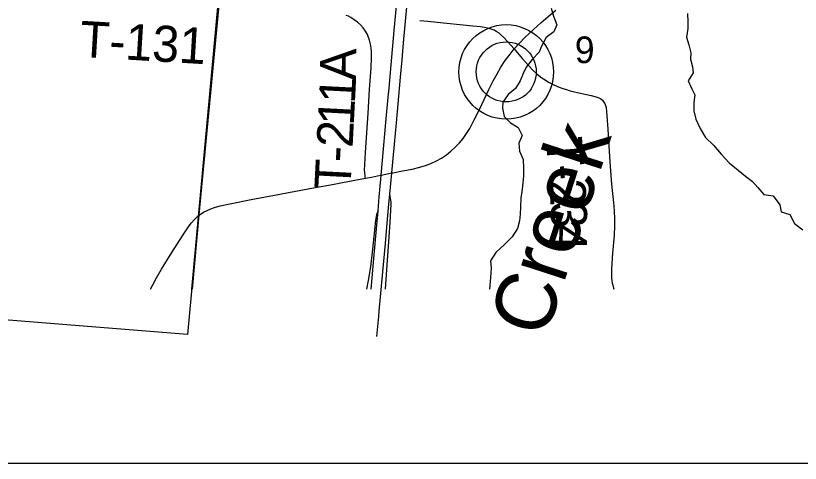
# Model space of a CAD drawing. Extents: x 0 to 34, y 0 to 22.
# Drawn here: x 6.536 to 7.77, y 17.5 to 18.205 of the extents above; entities that cross this region are included whole.
import ezdxf

# ---------------------------------------------------------------- set-up
doc = ezdxf.new("R2010")
doc.units = 0
for name, color, linetype in [('GM_X_Corporation', 7, 'Continuous'), ('GM_X_County_Road', 7, 'Continuous'), ('GM_X_Interchange_Ramps', 7, 'Continuous'), ('GM_X_Minor_River', 7, 'Continuous'), ('GM_X_Minor_River_Text', 7, 'Continuous'), ('GM_X_Section_Text', 7, 'Continuous'), ('GM_X_Township_Road', 7, 'Continuous'), ('GM_X_Township_Road_Text', 7, 'Continuous'), ('GM_X_Unincorporated', 7, 'Continuous'), ('GM_X_Unincorporated_Location', 7, 'Continuous'), ('GM_X_US_Route', 7, 'Continuous'), ('SH_Data', 7, 'Continuous')]:
    doc.layers.add(name, color=color, linetype=linetype)

msp = doc.modelspace()

# ---------------------------------------------------------------- linework, layer by layer
at = {"layer": 'GM_X_Corporation'}
for points in [[(6.8137, 17.7739), (6.8245, 17.8909), (6.8563, 18.2261), (6.9053, 18.781), (6.9106, 18.8306), (6.9204, 18.908), (6.8775, 18.9245), (6.8626, 18.9279), (6.8089, 18.9336), (6.7895, 18.937), (6.762, 18.9484), (6.7095, 18.9576), (6.6683, 18.9564), (6.6317, 18.9678), (6.5552, 18.9793), (6.4809, 18.9953)], [(6.4809, 18.9953), (6.5552, 18.9793), (6.6317, 18.9678), (6.6683, 18.9564), (6.7095, 18.9576), (6.762, 18.9484), (6.7895, 18.937), (6.8089, 18.9336), (6.8626, 18.9279), (6.8775, 18.9245), (6.9204, 18.908), (6.9106, 18.8306), (6.9053, 18.781), (6.8563, 18.2261), (6.8245, 17.8909), (6.8137, 17.7739)], [(6.8132, 17.7739), (6.9001, 18.7194), (7.9102, 18.6438), (7.8167, 17.7739)]]:
    msp.add_lwpolyline(points, dxfattribs=at)
msp.add_lwpolyline([(5.8857, 18.8), (6.9001, 18.7194), (6.8066, 17.7025), (5.8048, 17.783)], close=True, dxfattribs=at)
at = {"layer": 'GM_X_County_Road'}
for points in [[(7.0862, 17.9488), (7.0959, 17.9506), (7.105, 17.9524), (7.1112, 17.9537), (7.1278, 17.957), (7.1294, 17.9573), (7.1446, 17.9602), (7.1598, 17.9632), (7.1718, 17.9662), (7.1807, 17.9689), (7.1893, 17.9721), (7.1978, 17.9759), (7.2059, 17.9804), (7.2136, 17.9855), (7.2208, 17.9912), (7.2276, 17.9975), (7.234, 18.0042), (7.2399, 18.0113), (7.2453, 18.0189), (7.2502, 18.0267), (7.2575, 18.0404), (7.2657, 18.0571), (7.2802, 18.0881), (7.2872, 18.102), (7.2932, 18.1131), (7.2994, 18.1236), (7.3062, 18.1341), (7.3137, 18.1441), (7.3204, 18.1524), (7.3283, 18.1613), (7.337, 18.1701), (7.3504, 18.1829), (7.3619, 18.1932), (7.3737, 18.2034), (7.3855, 18.2134)], [(7.0372, 17.9396), (7.0501, 17.9421), (7.0862, 17.9488)], [(6.8248, 17.8903), (6.8264, 17.8916), (6.8317, 17.8951), (6.8373, 17.898), (6.843, 17.9006), (6.8489, 17.9027), (6.858, 17.9052), (6.8732, 17.9085), (6.9066, 17.9152), (6.9433, 17.9221), (6.9738, 17.9279), (7.0044, 17.9334), (7.0372, 17.9396)], [(6.7482, 17.7739), (6.7517, 17.7811), (6.7576, 17.7921), (6.7654, 17.8055), (6.7818, 17.8319), (6.7986, 17.8581), (6.8091, 17.8736), (6.8129, 17.8786), (6.817, 17.8833), (6.8215, 17.8877), (6.8248, 17.8903)]]:
    msp.add_lwpolyline(points, dxfattribs=at)
at = {"layer": 'GM_X_Interchange_Ramps'}
for points in [[(7.1176, 17.7739), (7.1181, 17.7819), (7.1208, 17.8199), (7.1228, 17.8485), (7.1251, 17.8797), (7.1269, 17.9076), (7.1267, 17.9111), (7.1263, 17.914), (7.1247, 17.9238)], [(7.1062, 17.8976), (7.1042, 17.8927), (7.1036, 17.891), (7.103, 17.8883), (7.102, 17.8821), (7.0975, 17.8371), (7.094, 17.8093), (7.0908, 17.7877), (7.0882, 17.7739)]]:
    msp.add_lwpolyline(points, dxfattribs=at)
at = {"layer": 'GM_X_Minor_River'}
for points in [[(7.3781, 18.2165), (7.3821, 18.2039), (7.3873, 18.1899), (7.3823, 18.1793), (7.3705, 18.1703), (7.3629, 18.1567), (7.3594, 18.1469), (7.3487, 18.1356), (7.3388, 18.1235), (7.3342, 18.1133), (7.3295, 18.102), (7.3223, 18.0899), (7.3105, 18.0805), (7.3021, 18.0684), (7.302, 18.0589), (7.3042, 18.046), (7.3143, 18.0357), (7.3267, 18.0284), (7.3327, 18.0159), (7.3277, 18.0038), (7.3283, 17.9913), (7.3343, 17.9783), (7.3349, 17.9643), (7.3349, 17.9518), (7.334, 17.9412), (7.3328, 17.9313), (7.3308, 17.9173), (7.33, 17.9037), (7.3295, 17.8919), (7.3287, 17.8817), (7.3255, 17.8696), (7.3171, 17.8567), (7.3053, 17.8451), (7.2912, 17.8319), (7.2828, 17.8187)], [(7.5929, 18.2081), (7.5935, 18.1948), (7.5935, 18.1846), (7.5911, 18.1709), (7.5948, 18.1588), (7.5981, 18.1459), (7.5976, 18.136), (7.6006, 18.1238), (7.6016, 18.1144), (7.594, 18.1019), (7.5996, 18.0894), (7.6044, 18.0798), (7.6028, 18.0681), (7.6027, 18.0548), (7.606, 18.0419), (7.6127, 18.0267), (7.6209, 18.013), (7.6344, 18.0004), (7.6457, 17.9866), (7.6585, 17.9729), (7.684, 17.9522), (7.6949, 17.9434), (7.7036, 17.9339), (7.7129, 17.9232), (7.7273, 17.9208), (7.7378, 17.9067), (7.7403, 17.8957), (7.7539, 17.8914), (7.761, 17.8777), (7.7742, 17.8674)], [(7.2828, 17.8187), (7.2838, 17.8069), (7.283, 17.7922), (7.2821, 17.7797), (7.2812, 17.7739)]]:
    msp.add_lwpolyline(points, dxfattribs=at)
at = {"layer": 'GM_X_Township_Road'}
for points in [[(7.0862, 17.9488), (7.086, 17.9509), (7.0851, 17.9582), (7.0849, 17.9611), (7.0865, 17.989), (7.0906, 18.051), (7.0929, 18.0882), (7.0952, 18.1224), (7.0959, 18.138), (7.0958, 18.1474), (7.0953, 18.1536), (7.0943, 18.1598), (7.0928, 18.166), (7.0908, 18.1719), (7.0895, 18.1748), (7.088, 18.1777), (7.0864, 18.1804), (7.0826, 18.1855), (7.0784, 18.1901), (7.0737, 18.1944), (7.0687, 18.1982), (7.0633, 18.2015), (7.0596, 18.2036), (7.0562, 18.205)], [(7.3204, 18.1524), (7.3096, 18.1639), (7.3033, 18.1707), (7.2989, 18.175), (7.2965, 18.177), (7.2931, 18.1793), (7.2885, 18.1816), (7.2839, 18.1833), (7.2782, 18.1848), (7.2735, 18.1858), (7.2674, 18.1868), (7.2551, 18.1881), (7.2397, 18.1898), (7.2088, 18.1927), (7.1842, 18.1953), (7.1718, 18.1963)], [(7.3204, 18.1524), (7.333, 18.1373), (7.3433, 18.1257), (7.3497, 18.1189), (7.3565, 18.1127), (7.3637, 18.1069), (7.3688, 18.1034), (7.374, 18.1001), (7.3823, 18.0959), (7.3907, 18.0921), (7.3967, 18.0899), (7.4023, 18.0881), (7.4083, 18.0864), (7.4264, 18.0823), (7.4415, 18.0787), (7.4505, 18.0762), (7.4534, 18.075), (7.4563, 18.0735), (7.4589, 18.0713), (7.4609, 18.069), (7.4626, 18.0662), (7.4638, 18.0632), (7.4646, 18.0601), (7.4654, 18.0538), (7.4674, 18.0259), (7.4702, 17.9826), (7.4712, 17.9671), (7.4733, 17.9393), (7.4742, 17.9296), (7.4751, 17.9197), (7.4768, 17.9053), (7.4776, 17.896), (7.478, 17.8866), (7.478, 17.8772), (7.4777, 17.871), (7.4774, 17.8617), (7.4772, 17.8586), (7.4748, 17.8307), (7.4734, 17.806), (7.4732, 17.7967), (7.4733, 17.7915), (7.4737, 17.7879), (7.4744, 17.7834), (7.4752, 17.7803), (7.4764, 17.7755), (7.4769, 17.7739)]]:
    msp.add_lwpolyline(points, dxfattribs=at)
at = {"layer": 'GM_X_Unincorporated'}
for radius in [0.0744, 0.0472]:
    msp.add_circle((7.3077, 18.116), radius, dxfattribs=at)
at = {"layer": 'GM_X_Unincorporated_Location'}
msp.add_line((7.3077, 18.116), (7.3077, 18.116), dxfattribs=at)
at = {"layer": 'GM_X_US_Route'}
for points in [[(7.1044, 17.6994), (7.1073, 17.7311), (7.1081, 17.7395), (7.1115, 17.7788), (7.1152, 17.8179), (7.1176, 17.8462), (7.1206, 17.8779), (7.1227, 17.9021), (7.1247, 17.9238), (7.1278, 17.957), (7.1321, 18.0024), (7.1349, 18.0359), (7.1375, 18.0658), (7.1413, 18.1076), (7.1438, 18.1349), (7.1462, 18.1617), (7.1512, 18.2181), (7.1525, 18.2332), (7.1535, 18.2451), (7.1563, 18.2771), (7.1587, 18.3023), (7.1643, 18.3633), (7.1665, 18.3876), (7.169, 18.4166)], [(7.0954, 17.7739), (7.0959, 17.7798), (7.0995, 17.8225), (7.1042, 17.8748), (7.1062, 17.8976), (7.1081, 17.9195), (7.1107, 17.9473), (7.1112, 17.9537), (7.1131, 17.9771), (7.1189, 18.042), (7.1221, 18.0764), (7.1234, 18.0907), (7.1268, 18.127), (7.1315, 18.1812), (7.1398, 18.2708)]]:
    msp.add_lwpolyline(points, dxfattribs=at)
at = {"layer": 'SH_Data'}
msp.add_line((2, 17.5), (9, 17.5), dxfattribs=at)

# ---------------------------------------------------------------- texts
at = {"layer": 'GM_X_Minor_River_Text'}
msp.add_text('Creek', height=0.09467, rotation=71.9853, dxfattribs=at).set_placement((7.3694, 17.6942))
at = {"layer": 'GM_X_Section_Text'}
msp.add_text('9', height=0.0419, rotation=0, dxfattribs=at).set_placement((7.4155, 18.1299))
at = {"layer": 'GM_X_Township_Road_Text'}
for s, height, rotation, p in [('T-131', 0.05682, 356.6344, (6.6359, 18.1398)), ('A', 0.0568, 89.0887, (7.0714, 18.1023)), ('1', 0.0568, 87.0482, (7.0696, 18.0654)), ('1', 0.0568, 87.0411, (7.0678, 18.0307)), ('2', 0.0568, 87.0408, (7.066, 17.996)), ('T', 0.0568, 274.354, (7.37, 18.0113)), ('-', 0.0568, 87.0408, (7.0648, 17.9729)), ('T', 0.0568, 87.0408, (7.0626, 17.9306)), ('-', 0.0568, 274.1799, (7.3732, 17.969)), ('2', 0.0568, 273.6296, (7.3749, 17.9459)), ('3', 0.0568, 272.2851, (7.3771, 17.9113)), ('4', 0.0568, 268.803, (7.3785, 17.8772))]:
    msp.add_text(s, height=height, rotation=rotation, dxfattribs=at).set_placement(p)

doc.saveas('drawing.dxf')
